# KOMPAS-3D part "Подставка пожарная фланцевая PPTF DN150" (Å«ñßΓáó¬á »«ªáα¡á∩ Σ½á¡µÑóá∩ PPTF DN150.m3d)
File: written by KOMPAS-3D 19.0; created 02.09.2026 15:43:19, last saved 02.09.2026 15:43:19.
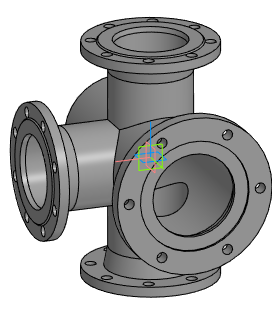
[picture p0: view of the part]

Document properties: Автор: Энергия; Полное имя файла: Z:\3.Личные\sachek\Dendor\_3D для проектировщиков\11.7 Тройник фланцевый с пожарной подставкой PPTF\PPTF_STP\Подставка пожарная фланцевая PPTF DN150.m3d

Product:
- Part/product: Подставка пожарная фланцевая PPTF DN150

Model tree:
1. Операция без истории:1  (labels: Подставка пожарная фланцевая PPTF DN150)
